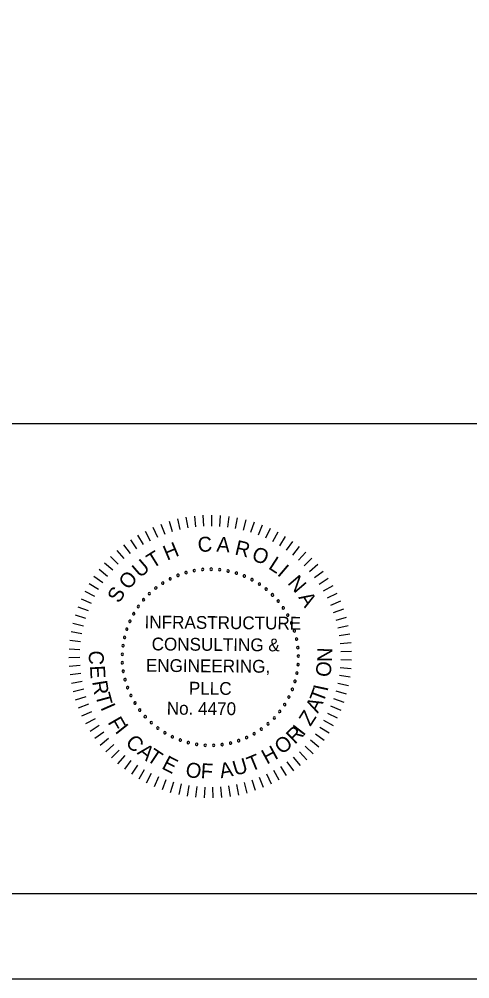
# Model space of a CAD drawing. Extents: x -121.2 to -24.9, y 6.4 to 66.3.
# Drawn here: x -53.92 to -46.89, y 6.35 to 21.33 of the extents above; entities that cross this region are included whole.
import ezdxf

# ---------------------------------------------------------------- set-up
doc = ezdxf.new("R2010")
doc.units = 0
for name, color, linetype in [('BR_BORDER LINES', 7, 'Continuous'), ('BR_TEXT', 7, 'Continuous'), ('Level 31', 7, 'Continuous')]:
    doc.layers.add(name, color=color, linetype=linetype)

msp = doc.modelspace()

# ---------------------------------------------------------------- linework, layer by layer
at = {"layer": 'BR_BORDER LINES'}
for p, q in [((-60.804, 15.017), (-46.496, 15.017)), ((-116.272, 7.683), (-26.496, 7.683))]:
    msp.add_line(p, q, dxfattribs=at)
at = {"layer": 'BR_TEXT'}
for p, q in [((-51.583, 13.49), (-51.533, 13.328)), ((-51.453, 13.526), (-51.413, 13.36)), ((-51.321, 13.553), (-51.292, 13.386)), ((-51.188, 13.572), (-51.169, 13.403)), ((-51.054, 13.583), (-51.045, 13.413)), ((-50.919, 13.586), (-50.921, 13.416)), ((-50.785, 13.58), (-50.796, 13.411)), ((-50.651, 13.567), (-50.673, 13.399)), ((-50.518, 13.545), (-50.55, 13.378)), ((-50.387, 13.515), (-50.429, 13.351)), ((-50.257, 13.478), (-50.31, 13.316)), ((-51.957, 13.338), (-51.878, 13.187)), ((-51.835, 13.396), (-51.766, 13.241)), ((-51.711, 13.447), (-51.651, 13.288)), ((-50.131, 13.432), (-50.193, 13.274)), ((-50.007, 13.379), (-50.079, 13.225)), ((-52.187, 13.2), (-52.091, 13.06)), ((-52.074, 13.272), (-51.987, 13.127)), ((-49.887, 13.318), (-49.968, 13.169)), ((-49.77, 13.251), (-49.86, 13.106)), ((-52.4, 13.034), (-52.287, 12.907)), ((-52.296, 13.12), (-52.192, 12.986)), ((-49.659, 13.176), (-49.757, 13.037)), ((-49.551, 13.094), (-49.658, 12.962)), ((-52.498, 12.942), (-52.378, 12.822)), ((-49.449, 13.006), (-49.564, 12.881)), ((-49.353, 12.913), (-49.475, 12.794)), ((-52.677, 12.741), (-52.543, 12.636)), ((-52.59, 12.844), (-52.463, 12.732)), ((-49.262, 12.813), (-49.391, 12.702)), ((-52.757, 12.633), (-52.617, 12.536)), ((-49.178, 12.708), (-49.313, 12.606)), ((-49.1, 12.598), (-49.242, 12.504)), ((-52.83, 12.52), (-52.684, 12.432)), ((-49.029, 12.484), (-49.176, 12.398)), ((-52.954, 12.281), (-52.799, 12.212)), ((-52.896, 12.402), (-52.745, 12.324)), ((-48.966, 12.365), (-49.117, 12.289)), ((-53.006, 12.157), (-52.847, 12.097)), ((-48.909, 12.243), (-49.065, 12.176)), ((-53.049, 12.029), (-52.887, 11.98)), ((-48.86, 12.117), (-49.02, 12.06)), ((-48.819, 11.989), (-48.982, 11.942)), ((-53.085, 11.9), (-52.92, 11.86)), ((-48.786, 11.859), (-48.951, 11.822)), ((-53.113, 11.768), (-52.946, 11.738)), ((-48.76, 11.727), (-48.928, 11.7)), ((-53.132, 11.635), (-52.964, 11.615)), ((-48.743, 11.593), (-48.912, 11.576)), ((-53.144, 11.501), (-52.974, 11.491)), ((-48.734, 11.459), (-48.904, 11.452)), ((-53.147, 11.366), (-52.978, 11.367)), ((-53.142, 11.231), (-52.973, 11.243)), ((-48.734, 11.324), (-48.903, 11.328)), ((-53.129, 11.097), (-52.961, 11.119)), ((-48.741, 11.19), (-48.91, 11.204)), ((-53.108, 10.965), (-52.941, 10.997)), ((-48.78, 10.923), (-48.947, 10.958)), ((-48.757, 11.056), (-48.925, 11.081)), ((-53.079, 10.833), (-52.914, 10.875)), ((-48.812, 10.793), (-48.976, 10.838)), ((-53.042, 10.704), (-52.88, 10.756)), ((-52.997, 10.577), (-52.838, 10.639)), ((-48.852, 10.664), (-49.013, 10.719)), ((-52.944, 10.453), (-52.79, 10.524)), ((-48.954, 10.415), (-49.107, 10.489)), ((-48.899, 10.538), (-49.056, 10.603)), ((-52.884, 10.333), (-52.734, 10.413)), ((-49.017, 10.296), (-49.165, 10.379)), ((-52.816, 10.216), (-52.672, 10.306)), ((-52.742, 10.104), (-52.603, 10.202)), ((-49.086, 10.181), (-49.229, 10.273)), ((-52.661, 9.996), (-52.529, 10.103)), ((-49.246, 9.964), (-49.376, 10.073)), ((-49.163, 10.07), (-49.3, 10.17)), ((-52.573, 9.894), (-52.448, 10.008)), ((-52.48, 9.797), (-52.362, 9.919)), ((-49.431, 9.768), (-49.547, 9.892)), ((-49.335, 9.863), (-49.459, 9.98)), ((-52.381, 9.706), (-52.27, 9.835)), ((-52.276, 9.622), (-52.173, 9.757)), ((-49.532, 9.679), (-49.64, 9.81)), ((-52.166, 9.543), (-52.072, 9.685)), ((-52.052, 9.472), (-51.967, 9.619)), ((-49.864, 9.451), (-49.947, 9.6)), ((-49.749, 9.521), (-49.841, 9.663)), ((-49.638, 9.597), (-49.738, 9.734)), ((-51.934, 9.408), (-51.858, 9.56)), ((-51.812, 9.351), (-51.745, 9.507)), ((-51.687, 9.302), (-51.629, 9.461)), ((-50.233, 9.288), (-50.288, 9.449)), ((-50.107, 9.335), (-50.171, 9.492)), ((-49.984, 9.389), (-50.058, 9.542)), ((-51.559, 9.26), (-51.511, 9.423)), ((-51.428, 9.226), (-51.391, 9.392)), ((-51.296, 9.2), (-51.269, 9.368)), ((-51.163, 9.183), (-51.146, 9.352)), ((-51.028, 9.173), (-51.022, 9.343)), ((-50.894, 9.172), (-50.898, 9.342)), ((-50.759, 9.179), (-50.773, 9.348)), ((-50.626, 9.194), (-50.65, 9.362)), ((-50.493, 9.217), (-50.528, 9.384)), ((-50.362, 9.249), (-50.407, 9.412))]:
    msp.add_line(p, q, dxfattribs=at)
for centre, start, end in [((-51.19, 12.72), 10.6038, 190.6038), ((-51.058, 12.738), 5.0653, 185.0653), ((-51.058, 12.738), 185.0653, 5.0653), ((-50.926, 12.743), 359.5268, 179.5268), ((-50.926, 12.743), 179.5268, 359.5268), ((-50.793, 12.735), 353.9884, 173.9884), ((-50.793, 12.735), 173.9884, 353.9884), ((-50.662, 12.714), 348.4499, 168.4499), ((-51.566, 12.592), 27.2191, 207.2191), ((-51.566, 12.592), 207.2191, 27.2191), ((-51.445, 12.647), 21.6807, 201.6807), ((-51.445, 12.647), 201.6807, 21.6807), ((-51.319, 12.689), 16.1422, 196.1422), ((-51.319, 12.689), 196.1422, 16.1422), ((-51.19, 12.72), 190.6038, 10.6038), ((-50.662, 12.714), 168.4499, 348.4499), ((-50.533, 12.681), 162.9114, 342.9114), ((-50.533, 12.681), 342.9114, 162.9114), ((-50.408, 12.636), 157.373, 337.373), ((-50.408, 12.636), 337.373, 157.373), ((-50.288, 12.579), 151.8345, 331.8345), ((-50.288, 12.579), 331.8345, 151.8345), ((-51.79, 12.449), 38.2961, 218.2961), ((-51.79, 12.449), 218.2961, 38.2961), ((-51.682, 12.526), 32.7576, 212.7576), ((-51.682, 12.526), 212.7576, 32.7576), ((-50.174, 12.51), 146.2961, 326.2961), ((-50.174, 12.51), 326.2961, 146.2961), ((-50.068, 12.431), 140.7576, 320.7576), ((-50.068, 12.431), 320.7576, 140.7576), ((-51.982, 12.265), 49.373, 229.373), ((-51.89, 12.362), 43.8345, 223.8345), ((-51.89, 12.362), 223.8345, 43.8345), ((-49.969, 12.342), 135.2191, 315.2191), ((-49.969, 12.342), 315.2191, 135.2191), ((-52.063, 12.16), 54.9114, 234.9114), ((-52.063, 12.16), 234.9114, 54.9114), ((-51.982, 12.265), 229.373, 49.373), ((-49.88, 12.244), 129.6807, 309.6807), ((-49.88, 12.244), 309.6807, 129.6807), ((-49.8, 12.137), 124.1422, 304.1422), ((-49.8, 12.137), 304.1422, 124.1422), ((-52.135, 12.048), 60.4499, 240.4499), ((-52.135, 12.048), 240.4499, 60.4499), ((-49.731, 12.024), 118.6038, 298.6038), ((-49.731, 12.024), 298.6038, 118.6038), ((-52.195, 11.93), 65.9884, 245.9884), ((-52.195, 11.93), 245.9884, 65.9884), ((-49.673, 11.904), 113.0653, 293.0653), ((-49.673, 11.904), 293.0653, 113.0653), ((-52.279, 11.678), 77.0653, 257.0653), ((-52.279, 11.678), 257.0653, 77.0653), ((-52.243, 11.806), 71.5268, 251.5268), ((-52.243, 11.806), 251.5268, 71.5268), ((-49.628, 11.779), 107.5268, 287.5268), ((-49.628, 11.779), 287.5268, 107.5268), ((-52.303, 11.547), 82.6038, 262.6038), ((-52.303, 11.547), 262.6038, 82.6038), ((-49.594, 11.651), 101.9884, 281.9884), ((-49.594, 11.651), 281.9884, 101.9884), ((-49.573, 11.519), 96.4499, 276.4499), ((-49.573, 11.519), 276.4499, 96.4499), ((-52.314, 11.415), 88.1422, 268.1422), ((-52.314, 11.415), 268.1422, 88.1422), ((-49.565, 11.387), 90.9114, 270.9114), ((-49.565, 11.387), 270.9114, 90.9114), ((-52.312, 11.282), 93.6807, 273.6807), ((-52.312, 11.282), 273.6807, 93.6807), ((-49.569, 11.254), 85.373, 265.373), ((-49.569, 11.254), 265.373, 85.373), ((-52.298, 11.15), 99.2191, 279.2191), ((-52.298, 11.15), 279.2191, 99.2191), ((-49.587, 11.122), 79.8345, 259.8345), ((-49.587, 11.122), 259.8345, 79.8345), ((-52.27, 11.02), 104.7576, 284.7576), ((-52.27, 11.02), 284.7576, 104.7576), ((-49.617, 10.993), 74.2961, 254.2961), ((-49.617, 10.993), 254.2961, 74.2961), ((-52.231, 10.893), 110.2961, 290.2961), ((-52.231, 10.893), 290.2961, 110.2961), ((-52.179, 10.771), 115.8345, 295.8345), ((-52.179, 10.771), 295.8345, 115.8345), ((-49.659, 10.867), 68.7576, 248.7576), ((-49.659, 10.867), 248.7576, 68.7576), ((-52.115, 10.654), 121.373, 301.373), ((-52.115, 10.654), 301.373, 121.373), ((-49.779, 10.63), 57.6807, 237.6807), ((-49.779, 10.63), 237.6807, 57.6807), ((-49.713, 10.746), 63.2191, 243.2191), ((-49.713, 10.746), 243.2191, 63.2191), ((-52.041, 10.544), 126.9114, 306.9114), ((-52.041, 10.544), 306.9114, 126.9114), ((-49.856, 10.522), 52.1422, 232.1422), ((-49.856, 10.522), 232.1422, 52.1422), ((-51.956, 10.441), 132.4499, 312.4499), ((-51.956, 10.441), 312.4499, 132.4499), ((-51.862, 10.348), 137.9884, 317.9884), ((-51.862, 10.348), 317.9884, 137.9884), ((-50.038, 10.329), 41.0653, 221.0653), ((-50.038, 10.329), 221.0653, 41.0653), ((-49.942, 10.421), 46.6038, 226.6038), ((-49.942, 10.421), 226.6038, 46.6038), ((-51.759, 10.263), 143.5268, 323.5268), ((-51.759, 10.263), 323.5268, 143.5268), ((-51.649, 10.189), 149.0653, 329.0653), ((-51.649, 10.189), 329.0653, 149.0653), ((-50.255, 10.175), 29.9884, 209.9884), ((-50.255, 10.175), 209.9884, 29.9884), ((-50.143, 10.247), 35.5268, 215.5268), ((-50.143, 10.247), 215.5268, 35.5268), ((-51.532, 10.126), 154.6038, 334.6038), ((-51.532, 10.126), 334.6038, 154.6038), ((-51.409, 10.075), 160.1422, 340.1422), ((-51.409, 10.075), 340.1422, 160.1422), ((-51.283, 10.036), 345.6807, 165.6807), ((-51.283, 10.036), 165.6807, 345.6807), ((-50.624, 10.029), 13.373, 193.373), ((-50.624, 10.029), 193.373, 13.373), ((-50.497, 10.066), 18.9114, 198.9114), ((-50.497, 10.066), 198.9114, 18.9114), ((-50.373, 10.115), 24.4499, 204.4499), ((-50.373, 10.115), 204.4499, 24.4499), ((-51.152, 10.009), 351.2191, 171.2191), ((-51.152, 10.009), 171.2191, 351.2191), ((-51.02, 9.995), 356.7576, 176.7576), ((-51.02, 9.995), 176.7576, 356.7576), ((-50.887, 9.993), 2.2961, 182.2961), ((-50.887, 9.993), 182.2961, 2.2961), ((-50.755, 10.005), 7.8345, 187.8345), ((-50.755, 10.005), 187.8345, 7.8345)]:
    msp.add_arc(centre, 0.0187, start, end, dxfattribs=at)
at = {"layer": 'Level 31'}
msp.add_lwpolyline([(-121.161, 6.35), (-25.161, 6.35), (-25.161, 65.017), (-121.161, 65.017)], close=True, dxfattribs=at)

# ---------------------------------------------------------------- texts
at = {"layer": 'BR_TEXT'}
for s, height, rotation, p in [('C', 0.233, 4.7281, (-51.127, 13.006)), ('A', 0.233, 355.6981, (-50.848, 13.019)), ('R', 0.233, 346.6681, (-50.57, 12.974)), ('T', 0.233, 31.8182, (-51.841, 12.747)), ('H', 0.233, 22.7882, (-51.615, 12.874)), ('O', 0.233, 337.638, (-50.31, 12.894)), ('U', 0.233, 40.8482, (-52.036, 12.597)), ('L', 0.233, 327.108, (-50.046, 12.759)), ('I', 0.233, 319.578, (-49.906, 12.659)), ('O', 0.233, 49.8782, (-52.215, 12.408)), ('N', 0.233, 310.548, (-49.744, 12.523)), ('S', 0.233, 58.9083, (-52.363, 12.199)), ('A', 0.233, 301.5179, (-49.57, 12.303)), ('INFRASTRUCTURE', 0.19939, 359.5268, (-51.966, 11.819)), ('CONSULTING &', 0.19939, 359.5268, (-51.856, 11.476)), ('C', 0.233, 267.025, (-52.829, 11.479)), ('N', 0.233, 89.2085, (-49.039, 11.293)), ('ENGINEERING,', 0.19939, 359.5268, (-51.946, 11.142)), ('O', 0.233, 83.2085, (-49.068, 11.05)), ('E', 0.233, 273.025, (-52.818, 11.235)), ('R', 0.233, 279.025, (-52.784, 10.989)), ('PLLC', 0.1994, 359.5268, (-51.275, 10.786)), ('T', 0.233, 285.025, (-52.737, 10.779)), ('T', 0.233, 69.3954, (-49.178, 10.645)), ('I', 0.233, 77.9093, (-49.11, 10.825)), ('I', 0.233, 293.7713, (-52.658, 10.584)), ('No. 4470', 0.1994, 359.5268, (-51.62, 10.474)), ('A', 0.233, 63.3954, (-49.26, 10.484)), ('Z', 0.233, 57.3954, (-49.377, 10.28)), ('F', 0.233, 299.7713, (-52.548, 10.355)), ('I', 0.233, 308.5268, (-52.436, 10.211)), ('R', 0.233, 44.5268, (-49.619, 10)), ('I', 0.233, 52.3339, (-49.487, 10.127)), ('C', 0.233, 314.5268, (-52.278, 10.024)), ('O', 0.233, 38.5268, (-49.823, 9.841)), ('A', 0.233, 320.5268, (-52.093, 9.868)), ('T', 0.233, 326.5268, (-51.948, 9.765)), ('H', 0.233, 28.5268, (-50.058, 9.691)), ('E', 0.233, 332.5268, (-51.712, 9.638)), ('U', 0.233, 16.5268, (-50.551, 9.515)), ('T', 0.233, 22.5268, (-50.306, 9.58)), ('O', 0.233, 350.5268, (-51.338, 9.508)), ('F', 0.233, 356.5268, (-51.094, 9.483)), ('A', 0.233, 10.5268, (-50.775, 9.479))]:
    msp.add_text(s, height=height, rotation=rotation, dxfattribs=at).set_placement(p)

doc.saveas('drawing.dxf')
